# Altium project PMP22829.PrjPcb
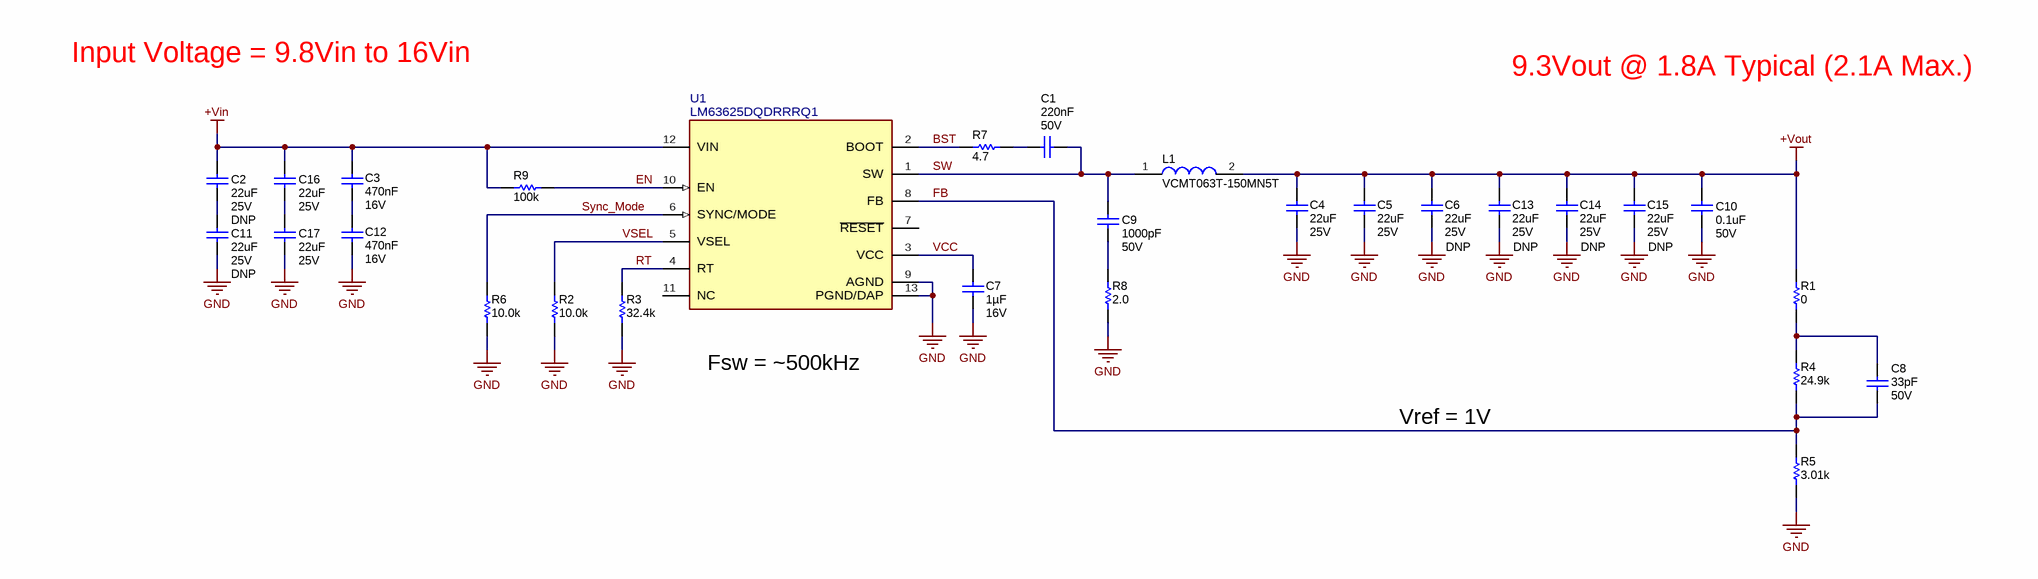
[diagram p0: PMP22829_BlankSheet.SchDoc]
CopyrightYear: 2020; PCB_Layout: Hrag Kasparian; PCB_Rev: A; PRJ_Engineer: Hrag Kasparian; PRJ_Number: PMP22829; PRJ_Title: LM63625 Small Solution Size Buck Regulator; SCH_Rev: 1; TechSupport: http://www.ti.com/support; TID: PMP22829
2 sheets, 30 parts. Net scope: global (net labels, ports and power ports of the same name join across sheets).
Board file: PMP22829_PCB.PcbDoc
Sheets:
  PMP22829_BlankSheet.SchDoc
  PMP22829_Hardware.SchDoc

## Sheet PMP22829_BlankSheet.SchDoc
size 431 x 279 mm; Date: Not shown in title block; ApprovedBy: Not shown in title block; CheckedBy: Not shown in title block; Author: Not shown in title block; CompanyName: Not shown in title block; Engineer: Not shown in title block; Organization: Not shown in title block; Address1: Not shown in title block; Address2: Not shown in title block; Address3: Not shown in title block; Address4: Not shown in title block; DocumentNumber: 2; Revision: Use project parameter SCH_Rev; SheetNumber: 2; SheetTotal: 3; PageSetup: Record=PageOptions¦CenterHorizontal=True¦CenterVertical=True¦PrintScale=1.00¦XCorrection=1.00¦YCorrection=1.00¦PrintKind=0¦BorderSize=5000000¦LeftOffset=0¦BottomOffset=0¦Orientation=2¦PaperLength=1000¦PaperWidth=1000¦Scale=100¦PaperSource=15¦PrintQuality=600¦MediaType=1¦DitherType=10¦PaperKind=Letter¦PrintScaleMode=1

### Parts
C1  Cap_F: 220nF  VDC_V: 50V  [0603L]  (hidden comment: GCM188R71H224KA64D)
C2  DNP  VDC_V: 25V  ValueDisplayed: 22uF  [0805L]
C3  Cap_F: 470nF  VDC_V: 16V  [0603]  (hidden comment: GCM188R71C474KA55D)
C4  ValueDisplayed: 22uF  VDC_V: 25V  [0805L]  (hidden comment: GRM21BR61E226ME44L)
C5  ValueDisplayed: 22uF  VDC_V: 25V  [0805L]  (hidden comment: GRM21BR61E226ME44L)
C6  DNP  ValueDisplayed: 22uF  VDC_V: 25V  [0805L]
C7  Cap_F: 1µF  VDC_V: 16V  [0603L]  (hidden comment: CGA3E1X7R1C105K080AC)
C8  VDC_V: 50V  ValueDisplayed: 33pF  [0402L]  (hidden comment: GCM1555C1H330JA16D)
C9  VDC_V: 50V  ValueDisplayed: 1000pF  [0402L]  (hidden comment: CGA2B2C0G1H102J050BA)
C10  VDC_V: 50V  ValueDisplayed: 0.1uF  [0402L]
C11  DNP  VDC_V: 25V  ValueDisplayed: 22uF  [0805L]
C12  Cap_F: 470nF  VDC_V: 16V  [0603]  (hidden comment: GCM188R71C474KA55D)
C13  DNP  ValueDisplayed: 22uF  VDC_V: 25V  [0805L]
C14  DNP  ValueDisplayed: 22uF  VDC_V: 25V  [0805L]
C15  DNP  ValueDisplayed: 22uF  VDC_V: 25V  [0805L]
C16  VDC_V: 25V  ValueDisplayed: 22uF  [0805L]  (hidden comment: GRM21BR61E226ME44L)
C17  VDC_V: 25V  ValueDisplayed: 22uF  [0805L]  (hidden comment: GRM21BR61E226ME44L)
L1  VCMT063T-150MN5T  [VCMT063T-150MN5TM]
R1  ValueDisplayed: 0  [0402L]  (hidden comment: ERJ-2GE0R00X)
R2  ValueDisplayed: 10.0k  [0402L]  (hidden comment: ERJ-2RKF1002X)
R3  ValueDisplayed: 32.4k  [0402L]  (hidden comment: CRCW040232K4FKED)
R4  ValueDisplayed: 24.9k  [0402]  (hidden comment: CRCW040224K9FKED)
R5  ValueDisplayed: 3.01k  [0402]  (hidden comment: CRCW04023K01FKED)
R6  ValueDisplayed: 10.0k  [0402L]  (hidden comment: ERJ-2RKF1002X)
R7  ValueDisplayed: 4.7  [0603L]  (hidden comment: CRCW06034R70JNEA)
R8  ValueDisplayed: 2.0  [0805L]  (hidden comment: CRCW08052R00JNEA)
R9  ValueDisplayed: 100k  [0402L]  (hidden comment: ERJ-2RKF1003X)
U1  LM63625DQDRRRQ1  [-MFG]

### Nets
+Vin: C2.1 C3.1 C16.1 R9.2 U1.12(VIN)
+Vout: C4.2 C5.2 C6.2 C10.1 C13.2 C14.2 C15.2 L1.2 R1.2
GND: C4.1 C5.1 C6.1 C7.2 C10.2 C11.2 C12.2 C13.1 C14.1 C15.1 C17.2 R2.1 R3.1 R5.1 R6.1 R8.1 U1.9(AGND) U1.13(PGND/DAP)
BST: R7.1 U1.2(BOOT)
EN: R9.1 U1.10(EN)
FB: C8.2 R4.1 R5.2 U1.8(FB)
RT: R3.2 U1.4(RT)
SW: C1.1 C9.1 L1.1 U1.1(SW)
Sync_Mode: R6.2 U1.6(SYNC/MODE)
VCC: C7.1 U1.3(VCC)
VSEL: R2.2 U1.5(VSEL)
NetC1_2: C1.2 R7.2
NetC2_2: C2.2 C11.1
NetC3_2: C3.2 C12.1
NetC8_1: C8.1 R1.1 R4.2
NetC9_2: C9.2 R8.2
NetC16_2: C16.2 C17.1

Not connected (* = marked no-connect by the designer): U1 7(~{RESET}) 11(NC)

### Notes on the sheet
- Input Voltage = 9.8Vin to 16Vin
- 9.3Vout @ 1.8A Typical (2.1A Max.)
- Fsw = ~500kHz
- Vref = 1V

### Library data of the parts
C1 = CMP-0007145-4: CAP, CERM, 0.22 uF, 50 V, +/- 10%, X7R, AEC-Q200 Grade 1, 0603; Manufacturer: MuRata; Polarized: N; Value: 0.22uF; U/M: EA; Value1: Unknown; TaMin_C: -55°C; SizeAreaWB_mm2: 4.68; TaMax_C: 125°C; SizeZ_mm: 1; SizeX_mm: 1.6; SizeY_mm: 0.8; Cap_Case: 0603; SizeArea_mm2: 1.28; AEC Qualified: Y; AEC Category: Q200
C2 = CMP-0008305-2: CAP, CERM, 22 uF, 25 V, +/- 20%, X5R, 0805; Manufacturer: MuRata; PartNumber: GRM21BR61E226ME44L; Polarized: N; Value: 22uF; U/M: EA; TaMin_C: -55°C; SizeAreaWB_mm2: 6.75; Value1: Unknown; TaMax_C: 85°C; SizeZ_mm: 1.45; SizeX_mm: 2; SizeY_mm: 1.25; Cap_Case: 0805; SizeArea_mm2: 2.5; Cap_F: 22µF; AEC Category: Q200
C3 C12 = CMP-0007138-4: CAP, CERM, 0.47 uF, 16 V, +/- 10%, X7R, AEC-Q200 Grade 1, 0603; Manufacturer: MuRata; TaMin_C: -55°C; Polarized: N; SizeAreaWB_mm2: 4.68; Value1: Unknown; U/M: EA; Value: 0.47uF; TaMax_C: 125°C; SizeZ_mm: 1; SizeX_mm: 1.6; SizeY_mm: 0.8; SizeArea_mm2: 1.28; AEC Qualified: Y; AEC Category: Q200
C4 C5 = CMP-0008305-2: CAP, CERM, 22 uF, 25 V, +/- 20%, X5R, 0805; Manufacturer: MuRata; Value: 22uF; AEC Qualified: N; SizeZ_mm: 1.45; Cap_F: 22µF; TaMin_C: -55°C; SizeAreaWB_mm2: 6.75; Value1: Unknown; U/M: EA; TaMax_C: 85°C; SizeX_mm: 2; SizeY_mm: 1.25; Cap_Case: 0805; SizeArea_mm2: 2.5; AEC Category: Q200
C6 C13-C15 = CMP-0008305-2: CAP, CERM, 22 uF, 25 V, +/- 20%, X5R, 0805; Manufacturer: MuRata; PartNumber: GRM21BR61E226ME44L; Value: 22uF; AEC Qualified: N; SizeZ_mm: 1.45; Cap_F: 22µF; TaMin_C: -55°C; SizeAreaWB_mm2: 6.75; Value1: Unknown; U/M: EA; TaMax_C: 85°C; SizeX_mm: 2; SizeY_mm: 1.25; Cap_Case: 0805; SizeArea_mm2: 2.5; AEC Category: Q200
C7 = CMP-0079607-1: CAP, CERM, 1 µF, 16 V,+/- 10%, X7R, AEC-Q200 Grade 1, 0603; Manufacturer: TDK; TaMin_C: -55°C; Polarized: N; SizeAreaWB_mm2: 4.68; U/M: EA; Value: 1uF; TaMax_C: 125°C; SizeZ_mm: 1; SizeX_mm: 1.6; SizeY_mm: 0.8; Cap_Case: 0603; SizeArea_mm2: 1.28; AEC Qualified: Y; AEC Category: Q200
C8 = CMP-0860833-1: CAP, CERM, 33 pF, 50 V,+/- 5%, C0G/NP0, AEC-Q200 Grade 1, 0402; Manufacturer: MuRata; AEC Qualified: Y; AEC Grade: 1; Value: 33pF; SizeZ_mm: 0.6; TaMin_C: -55°C; Polarized: N; SizeAreaWB_mm2: 3; U/M: EA; TaMax_C: 125°C; SizeY_mm: 0.5; Cap_Case: 0402; AEC Category: Q200
C9 = CMP-0006309-2: CAP, CERM, 1000 pF, 50 V, +/- 5%, C0G/NP0, AEC-Q200 Grade 1, 0402; Manufacturer: TDK; TaMin_C: -55°C; Polarized: N; SizeAreaWB_mm2: 3; Value1: Unknown; U/M: EA; Value: 1000pF; TaMax_C: 125°C; SizeZ_mm: 0.6; SizeX_mm: 1; SizeY_mm: 0.5; Cap_Case: 0402; AEC Qualified: Y; Cap_F: 1nF; AEC Category: Q200
C10 = CMP-0006356-2: CAP, CERM, 0.1 uF, 50 V, +/- 10%, X7R, AEC-Q200 Grade 1, 0402; Manufacturer: MuRata; PartNumber: GCM155R71H104KE02D; TaMin_C: -55°C; Polarized: N; SizeAreaWB_mm2: 3; Value1: Unknown; U/M: EA; Value: 0.1uF; TaMax_C: 125°C; SizeZ_mm: 0.6; SizeX_mm: 1; SizeY_mm: 0.5; Cap_Case: 0402; AEC Qualified: Y; Cap_F: 100nF; AEC Category: Q200
C11 = CMP-0008305-2: CAP, CERM, 22 uF, 25 V, +/- 20%, X5R, 0805; Manufacturer: MuRata; PartNumber: GRM21BR61E226ME44L; TaMin_C: -55°C; Polarized: N; SizeAreaWB_mm2: 6.75; Value1: Unknown; U/M: EA; Value: 22uF; TaMax_C: 85°C; SizeZ_mm: 1.45; SizeX_mm: 2; SizeY_mm: 1.25; Cap_Case: 0805; SizeArea_mm2: 2.5; Cap_F: 22µF; AEC Category: Q200
C16 = CMP-0008305-2: CAP, CERM, 22 uF, 25 V, +/- 20%, X5R, 0805; Manufacturer: MuRata; Polarized: N; Value: 22uF; U/M: EA; TaMin_C: -55°C; SizeAreaWB_mm2: 6.75; Value1: Unknown; TaMax_C: 85°C; SizeZ_mm: 1.45; SizeX_mm: 2; SizeY_mm: 1.25; Cap_Case: 0805; SizeArea_mm2: 2.5; Cap_F: 22µF; AEC Category: Q200
C17 = CMP-0008305-2: CAP, CERM, 22 uF, 25 V, +/- 20%, X5R, 0805; Manufacturer: MuRata; TaMin_C: -55°C; Polarized: N; SizeAreaWB_mm2: 6.75; Value1: Unknown; U/M: EA; Value: 22uF; TaMax_C: 85°C; SizeZ_mm: 1.45; SizeX_mm: 2; SizeY_mm: 1.25; Cap_Case: 0805; SizeArea_mm2: 2.5; Cap_F: 22µF; AEC Category: Q200
L1 = VCMT063T-150MN5TM: Manufacturer: Cyntec; CompType: Inductor; Value: 15uH
R1 = CMP-0026992-3: RES, 0, 5%, 0.1 W, AEC-Q200 Grade 0, 0402; Manufacturer: Panasonic; Power_W: 100mW; TempCo: 600 ppm/C; Value_Code: 0000; Value: 0; EIA_Code: E24; SizeX_mm: 1; SizeY_mm: 0.5; SizeZ_mm: 0.6; Value2: 0.1W; AEC Qualified: Y; VDC_V: 50V; AEC Category: Q200; SizeAreaWB_mm2: 3
R2 R6 = CMP-0026658-1: RES, 10.0 k, 1%, 0.1 W, 0402; Manufacturer: Panasonic; Power_W: 100mW; TempCo: 100 ppm/C; Value_Code: 10k0; U/M: EA; Value: 10.0k; EIA_Code: E96; Res_ohm: 10k; SizeX_mm: 1; SizeY_mm: 0.5; SizeZ_mm: 0.6; Value2: 0.1W; VDC_V: 50V; AEC Category: Q200
R3 = CMP-0026294-2: RES, 32.4 k, 1%, 0.063 W, AEC-Q200 Grade 0, 0402; Manufacturer: Vishay-Dale; Value: 32.4k; Power_W: 63mW; TempCo: 100 ppm/C; Value_Code: 32k4; EIA_Code: E96; SizeX_mm: 1; SizeY_mm: 0.5; SizeZ_mm: 0.6; Value2: 0.063W; AEC Qualified: Y; VDC_V: 50V; AEC Category: Q200; AEC Grade: 0
R4 = CMP-0026196-2: RES, 24.9 k, 1%, 0.063 W, AEC-Q200 Grade 0, 0402; Manufacturer: Vishay-Dale; Value2: 0.063W; EIA_Code: E96; Value: 24.9k; SizeArea_mm2: 0.5; TempCo: 100 ppm/C; SizeZ_mm: 0.6; AEC Category: Q200; Value_Code: 24k9; VDC_V: 50V; Power_W: 63mW; AEC Grade: 0; SizeX_mm: 1; AEC Qualified: Y
R5 = CMP-0026329-2: RES, 3.01 k, 1%, 0.063 W, AEC-Q200 Grade 0, 0402; Manufacturer: Vishay-Dale; Value: 3.01k; Power_W: 63mW; TempCo: 100 ppm/C; Value_Code: 3k01; EIA_Code: E96; SizeX_mm: 1; SizeY_mm: 0.5; SizeZ_mm: 0.6; Value2: 0.063W; AEC Qualified: Y; VDC_V: 50V; AEC Category: Q200; AEC Grade: 0
R7 = CMP-0025821-4: RES, 4.7, 5%, 0.1 W, AEC-Q200 Grade 0, 0603; Manufacturer: Vishay-Dale; Power_W: 100mW; TempCo: 200 ppm/C; Value_Code: 4R70; Value: 4.7; EIA_Code: E24; SizeX_mm: 1.6; SizeY_mm: 0.8; SizeZ_mm: 1; Value2: 0.1W; SizeArea_mm2: 1.28; AEC Qualified: Y; VDC_V: 75V; AEC Category: Q200; AEC Grade: 0
R8 = CMP-0020518-3: RES, 2.0, 5%, 0.125 W, AEC-Q200 Grade 0, 0805; Manufacturer: Vishay-Dale; Power_W: 125mW; TempCo: 200 ppm/C; Value_Code: 2R00; Value: 2.0; EIA_Code: E24; Res_ohm: 2; SizeY_mm: 1.25; SizeZ_mm: 1.45; Value2: 0.125W; SizeArea_mm2: 2.5; AEC Qualified: Y; VDC_V: 150V; AEC Category: Q200; AEC Grade: 0
R9 = CMP-0026659-2: RES, 100 k, 1%, 0.1 W, 0402; Manufacturer: Panasonic; U/M: EA; Value2: 0.1W; EIA_Code: E96; Value: 100k; SizeArea_mm2: 0.5; TempCo: 100 ppm/C; SizeZ_mm: 0.6; AEC Category: Q200; VDC_V: 50V; Power_W: 100mW; AEC Grade: 0; SizeX_mm: 1; AEC Qualified: Yes
U1 = CMP-0088323-1: 3.5-V to 36-V, 2.5-A Automotive Step-down Voltage Converter; Manufacturer: Texas Instruments; SizeZ_mm: 0.8mm; Switching Topology: Buck; Output Type: AdjustableProgrammable; Standoff Height: 0mm; Max Supply Voltage: 36V; Nominal Supply Current: 23uA; Switching Frequency: 250-2200kHz; TaMin_C: -40°C; Number Of Outputs: 1; TJmax_C: +150°C; AEC Grade: Grade 1; Min Supply Voltage: 3.5V; Max Duty Cycle: 98%; TaMax_C: +125°C; AEC Qualified: Yes; Output Voltage: 1-20V

## Sheet PMP22829_Hardware.SchDoc
size 431 x 279 mm; Date: Not shown in title block; ApprovedBy: Not shown in title block; CheckedBy: Not shown in title block; Author: Not shown in title block; CompanyName: Not shown in title block; Engineer: Not shown in title block; Organization: Not shown in title block; Address1: Not shown in title block; Address2: Not shown in title block; Address3: Not shown in title block; Address4: Not shown in title block; DocumentNumber: 3; Revision: Use project parameter SCH_Rev; SheetNumber: 3; SheetTotal: 3; PageSetup: Record=PageOptions¦CenterHorizontal=True¦CenterVertical=True¦PrintScale=1.00¦XCorrection=1.00¦YCorrection=1.00¦PrintKind=0¦BorderSize=5000000¦LeftOffset=0¦BottomOffset=0¦Orientation=2¦PaperLength=1000¦PaperWidth=1000¦Scale=100¦PaperSource=15¦PrintQuality=600¦MediaType=1¦DitherType=10¦PaperKind=Letter¦PrintScaleMode=1
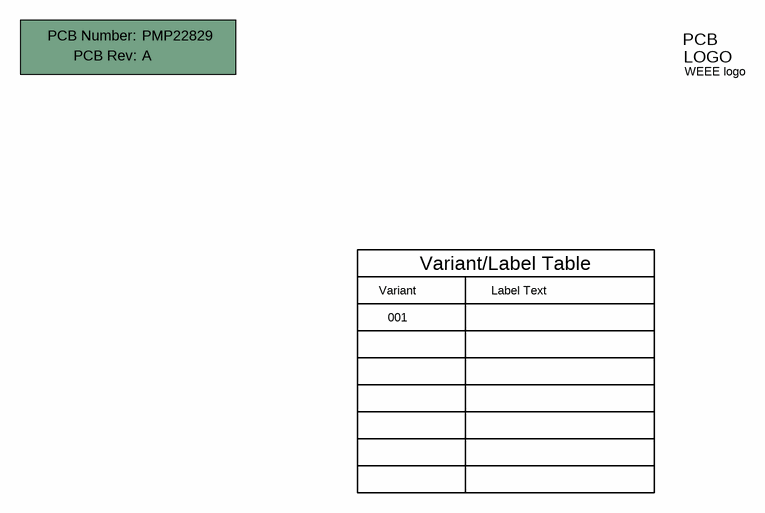
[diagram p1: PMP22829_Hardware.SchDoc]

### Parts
!PCB1  Printed Circuit Board  (value not drawn)  (mechanical)
Logo1  WEEE logo  [WEEE_Minimum]  (no BOM)

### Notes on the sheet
- Variant
- Variant/Label Table
- Label Text
- 001

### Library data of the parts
!PCB1 = CMP-0003618-2: Manufacturer: Any; PartNumber: PMP22829
Logo1 = CMP-0074769-1

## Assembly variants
001: not fitted C2 C6 C11 C13 C14 C15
